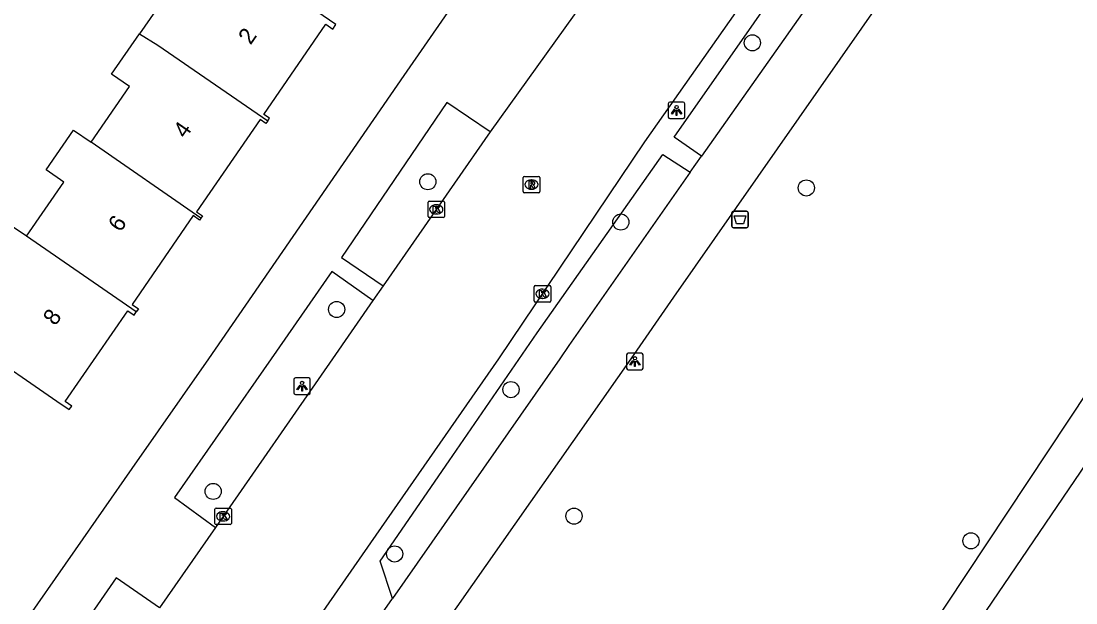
# Model space of a CAD drawing. Extents: x 160158 to 160921, y 381517 to 382041.
# Drawn here: x 160728 to 160791.9, y 381735.2 to 381770.5 of the extents above; entities that cross this region are included whole.
import ezdxf

# ---------------------------------------------------------------- set-up
doc = ezdxf.new("R2010")
doc.units = 0
for name, color, linetype in [('IMGEO_Afvalbak', 7, 'Continuous'), ('IMGEO_Boom', 7, 'Continuous'), ('IMGEO_Fietspad_open', 7, 'Continuous'), ('IMGEO_Kolk', 7, 'Continuous'), ('IMGEO_Lichtpunt', 7, 'Continuous'), ('IMGEO_Loofbos', 7, 'Continuous'), ('IMGEO_Pand', 7, 'Continuous'), ('IMGEO_Pand_nummerreeks', 7, 'Continuous'), ('IMGEO_Rijbaan_lokaal_open', 7, 'Continuous'), ('IMGEO_Rioolput', 7, 'Continuous'), ('IMGEO_Voetpad_open', 7, 'Continuous'), ('IMGEO_Waterloop', 7, 'Continuous')]:
    doc.layers.add(name, color=color, linetype=linetype)

msp = doc.modelspace()

# ---------------------------------------------------------------- linework, layer by layer
at = {"layer": 'IMGEO_Afvalbak'}
for p, q in [((160771.04, 381758.034), (160771.04, 381758.834)), ((160771.04, 381758.834), (160771.04, 381758.034)), ((160771.14, 381758.934), (160771.93, 381758.934)), ((160771.93, 381758.934), (160771.14, 381758.934)), ((160772.03, 381758.834), (160772.03, 381758.034)), ((160772.03, 381758.034), (160772.03, 381758.834)), ((160771.93, 381757.934), (160771.14, 381757.934)), ((160771.14, 381757.934), (160771.93, 381757.934))]:
    msp.add_line(p, q, dxfattribs=at)
msp.add_lwpolyline([(160771.183, 381758.648), (160771.887, 381758.648), (160771.738, 381758.178), (160771.332, 381758.178), (160771.183, 381758.648)], dxfattribs=at)
for centre, start, end in [((160771.14, 381758.834), 90, 180), ((160771.14, 381758.834), 90, 180), ((160771.93, 381758.834), 0, 90), ((160771.93, 381758.834), 360, 90), ((160771.14, 381758.034), 180, 270), ((160771.14, 381758.034), 180, 270), ((160771.93, 381758.034), 270, 0), ((160771.93, 381758.034), 270, 0)]:
    msp.add_arc(centre, 0.1, start, end, dxfattribs=at)
at = {"layer": 'IMGEO_Boom'}
for centre in [(160772.285, 381769.136), (160752.634, 381760.719), (160775.548, 381760.345), (160764.32, 381758.278), (160747.113, 381752.984), (160757.667, 381748.128), (160739.639, 381741.96), (160761.485, 381740.463), (160785.516, 381738.965), (160750.624, 381738.171)]:
    msp.add_circle(centre, 0.489, dxfattribs=at)
at = {"layer": 'IMGEO_Fietspad_open'}
for points in [[(160789.665, 381791.308), (160769.212, 381762.274)], [(160792.763, 381789.478), (160791.434, 381788.016), (160767.517, 381753.72), (160764.918, 381750), (160753.579, 381733.814)], [(160768.522, 381761.29), (160769.212, 381762.274)], [(160768.522, 381761.29), (160761.166, 381750.794), (160760.618, 381750), (160750.493, 381735.463)], [(160747.881, 381731.718), (160750.493, 381735.463)]]:
    msp.add_lwpolyline(points, dxfattribs=at)
at = {"layer": 'IMGEO_Kolk'}
for p, q in [((160752.645, 381758.621), (160752.645, 381759.473)), ((160752.72, 381759.547), (160753.572, 381759.547)), ((160753.133, 381759.327), (160753.158, 381759.327)), ((160753.646, 381759.473), (160753.646, 381758.621)), ((160753.572, 381758.547), (160752.72, 381758.547)), ((160753.156, 381758.767), (160753.131, 381758.767)), ((160759.079, 381753.506), (160759.079, 381754.358)), ((160759.154, 381754.432), (160760.006, 381754.432)), ((160759.567, 381754.212), (160759.592, 381754.212)), ((160760.08, 381754.358), (160760.08, 381753.506)), ((160760.006, 381753.432), (160759.154, 381753.432)), ((160759.59, 381753.652), (160759.565, 381753.652)), ((160739.738, 381740.024), (160739.738, 381740.876)), ((160739.813, 381740.95), (160740.665, 381740.95)), ((160740.226, 381740.73), (160740.251, 381740.73)), ((160740.739, 381740.876), (160740.739, 381740.024)), ((160740.665, 381739.95), (160739.813, 381739.95)), ((160740.249, 381740.17), (160740.224, 381740.17))]:
    msp.add_line(p, q, dxfattribs=at)
for points in [[(160752.645, 381758.621), (160752.645, 381759.473)], [(160752.72, 381759.547), (160753.572, 381759.547)], [(160752.966, 381759.247), (160753.089, 381759.247), (160753.089, 381759.096), (160753.219, 381759.247), (160753.383, 381759.247), (160753.237, 381759.096), (160753.39, 381758.847), (160753.238, 381758.847), (160753.153, 381759.011), (160753.089, 381758.944), (160753.089, 381758.847), (160752.966, 381758.847), (160752.966, 381759.247)], [(160753.646, 381759.473), (160753.646, 381758.621)], [(160753.572, 381758.547), (160752.72, 381758.547)], [(160759.079, 381753.506), (160759.079, 381754.358)], [(160759.154, 381754.432), (160760.006, 381754.432)], [(160759.4, 381754.132), (160759.523, 381754.132), (160759.523, 381753.981), (160759.653, 381754.132), (160759.817, 381754.132), (160759.671, 381753.981), (160759.824, 381753.732), (160759.672, 381753.732), (160759.587, 381753.896), (160759.523, 381753.829), (160759.523, 381753.732), (160759.4, 381753.732), (160759.4, 381754.132)], [(160760.08, 381754.358), (160760.08, 381753.506)], [(160760.006, 381753.432), (160759.154, 381753.432)], [(160739.738, 381740.024), (160739.738, 381740.876)], [(160739.813, 381740.95), (160740.665, 381740.95)], [(160740.059, 381740.65), (160740.182, 381740.65), (160740.182, 381740.499), (160740.312, 381740.65), (160740.476, 381740.65), (160740.33, 381740.499), (160740.483, 381740.25), (160740.331, 381740.25), (160740.246, 381740.414), (160740.182, 381740.347), (160740.182, 381740.25), (160740.059, 381740.25), (160740.059, 381740.65)], [(160740.739, 381740.876), (160740.739, 381740.024)], [(160740.665, 381739.95), (160739.813, 381739.95)]]:
    msp.add_lwpolyline(points, dxfattribs=at)
for centre, start, end in [((160752.722, 381759.471), 91.55205, 178.44795), ((160752.722, 381759.471), 91.55205, 178.44795), ((160753.57, 381759.471), 1.55205, 88.44795), ((160753.57, 381759.471), 1.55205, 88.44795), ((160752.722, 381758.623), 181.55205, 268.44795), ((160752.722, 381758.623), 181.55205, 268.44795), ((160753.57, 381758.623), 271.55205, 358.44795), ((160753.57, 381758.623), 271.55205, 358.44795), ((160759.156, 381754.356), 91.55205, 178.44795), ((160759.156, 381754.356), 91.55205, 178.44795), ((160760.004, 381754.356), 1.55205, 88.44795), ((160760.004, 381754.356), 1.55205, 88.44795), ((160759.156, 381753.508), 181.55205, 268.44795), ((160759.156, 381753.508), 181.55205, 268.44795), ((160760.004, 381753.508), 271.55205, 358.44795), ((160760.004, 381753.508), 271.55205, 358.44795), ((160739.815, 381740.874), 91.55205, 178.44795), ((160739.815, 381740.874), 91.55205, 178.44795), ((160740.663, 381740.874), 1.55205, 88.44795), ((160740.663, 381740.874), 1.55205, 88.44795), ((160739.815, 381740.026), 181.55205, 268.44795), ((160739.815, 381740.026), 181.55205, 268.44795), ((160740.663, 381740.026), 271.55205, 358.44795), ((160740.663, 381740.026), 271.55205, 358.44795)]:
    msp.add_arc(centre, 0.0765, start, end, dxfattribs=at)
for centre, major_axis, ratio, start_param, end_param in [((160753.132, 381759.047), (-0.387, 0.002), 0.722429, 4.712389, 7.853982), ((160753.157, 381759.047), (-0.39, 0.002), 0.717154, 1.570796, 4.712389), ((160759.566, 381753.932), (-0.387, 0.002), 0.722429, 4.712389, 7.853982), ((160759.591, 381753.932), (-0.39, 0.002), 0.717154, 1.570796, 4.712389), ((160740.225, 381740.45), (-0.387, 0.002), 0.722429, 4.712389, 7.853982), ((160740.25, 381740.45), (-0.39, 0.002), 0.717154, 1.570796, 4.712389)]:
    msp.add_ellipse(centre, major_axis=major_axis, ratio=ratio, start_param=start_param, end_param=end_param, dxfattribs=at)
at = {"layer": 'IMGEO_Lichtpunt'}
for p, q in [((160767.194, 381765.448), (160767.194, 381764.641)), ((160767.194, 381765.448), (160767.194, 381764.641)), ((160768.096, 381765.543), (160767.288, 381765.543)), ((160768.096, 381765.543), (160767.288, 381765.543)), ((160768.19, 381764.641), (160768.19, 381765.448)), ((160768.19, 381764.641), (160768.19, 381765.448)), ((160767.288, 381764.547), (160768.096, 381764.547)), ((160767.288, 381764.547), (160768.096, 381764.547)), ((160764.672, 381750.232), (160764.672, 381749.425)), ((160764.672, 381750.232), (160764.672, 381749.425)), ((160765.574, 381750.327), (160764.766, 381750.327)), ((160765.574, 381750.327), (160764.766, 381750.327)), ((160765.668, 381749.425), (160765.668, 381750.232)), ((160765.668, 381749.425), (160765.668, 381750.232)), ((160745.426, 381748.834), (160744.618, 381748.834)), ((160745.426, 381748.834), (160744.618, 381748.834)), ((160764.766, 381749.331), (160765.574, 381749.331)), ((160764.766, 381749.331), (160765.574, 381749.331)), ((160744.524, 381748.739), (160744.524, 381747.932)), ((160744.524, 381748.739), (160744.524, 381747.932)), ((160745.52, 381747.932), (160745.52, 381748.739)), ((160745.52, 381747.932), (160745.52, 381748.739)), ((160744.618, 381747.838), (160745.426, 381747.838)), ((160744.618, 381747.838), (160745.426, 381747.838))]:
    msp.add_line(p, q, dxfattribs=at)
for points in [[(160767.568, 381765.112), (160767.607, 381765.084), (160767.419, 381764.822), (160767.381, 381764.849), (160767.568, 381765.112)], [(160767.67, 381765.064), (160767.717, 381765.064), (160767.717, 381764.742), (160767.67, 381764.742), (160767.67, 381765.064)], [(160767.78, 381765.084), (160767.818, 381765.111), (160768.005, 381764.849), (160767.966, 381764.821), (160767.78, 381765.084)], [(160765.046, 381749.896), (160765.085, 381749.868), (160764.897, 381749.606), (160764.859, 381749.633), (160765.046, 381749.896)], [(160765.148, 381749.848), (160765.195, 381749.848), (160765.195, 381749.526), (160765.148, 381749.526), (160765.148, 381749.848)], [(160765.258, 381749.868), (160765.296, 381749.895), (160765.483, 381749.633), (160765.444, 381749.605), (160765.258, 381749.868)], [(160744.898, 381748.403), (160744.937, 381748.375), (160744.749, 381748.113), (160744.711, 381748.14), (160744.898, 381748.403)], [(160745, 381748.355), (160745.047, 381748.355), (160745.047, 381748.033), (160745, 381748.033), (160745, 381748.355)], [(160745.11, 381748.375), (160745.148, 381748.402), (160745.335, 381748.14), (160745.296, 381748.112), (160745.11, 381748.375)]]:
    msp.add_lwpolyline(points, dxfattribs=at)
for centre in [(160767.693, 381765.246), (160765.171, 381750.03), (160745.023, 381748.537)]:
    msp.add_circle(centre, 0.0994, dxfattribs=at)
for centre, start, end in [((160767.288, 381765.448), 90, 180), ((160767.288, 381765.448), 90, 180), ((160768.096, 381765.448), 0, 90), ((160768.096, 381765.448), 0, 90), ((160767.288, 381764.641), 180, 270), ((160767.288, 381764.641), 180, 270), ((160768.096, 381764.641), 270, 0), ((160768.096, 381764.641), 270, 360), ((160764.766, 381750.232), 90, 180), ((160764.766, 381750.232), 90, 180), ((160765.574, 381750.232), 0, 90), ((160765.574, 381750.232), 0, 90), ((160764.766, 381749.425), 180, 270), ((160764.766, 381749.425), 180, 270), ((160765.574, 381749.425), 270, 0), ((160765.574, 381749.425), 270, 360), ((160744.618, 381748.739), 90, 180), ((160744.618, 381748.739), 90, 180), ((160745.426, 381748.739), 0, 90), ((160745.426, 381748.739), 0, 90), ((160744.618, 381747.932), 180, 270), ((160744.618, 381747.932), 180, 270), ((160745.426, 381747.932), 270, 0), ((160745.426, 381747.932), 270, 360)]:
    msp.add_arc(centre, 0.0946, start, end, dxfattribs=at)
at = {"layer": 'IMGEO_Loofbos'}
msp.add_lwpolyline([(160806.201, 381767.868), (160793.894, 381750), (160774.154, 381720.209)], dxfattribs=at)
at = {"layer": 'IMGEO_Pand'}
for points in [[(160742.941, 381764.412), (160743.047, 381764.566), (160742.704, 381764.802), (160746.455, 381770.258), (160746.878, 381769.967), (160747.068, 381770.245), (160739.262, 381775.612), (160737.435, 381772.955), (160735.18, 381769.69)], [(160732.259, 381763.116), (160734.577, 381766.489), (160733.492, 381767.235), (160735.18, 381769.69)], [(160735.18, 381769.69), (160736.285, 381768.99), (160742.941, 381764.412)], [(160742.941, 381764.412), (160742.832, 381764.253), (160742.481, 381764.494), (160738.63, 381758.892), (160738.985, 381758.648), (160738.9, 381758.523)], [(160728.339, 381757.419), (160730.593, 381760.699), (160729.527, 381761.432), (160731.19, 381763.851), (160732.259, 381763.116)], [(160738.9, 381758.523), (160732.259, 381763.116)], [(160738.9, 381758.523), (160738.813, 381758.397), (160738.423, 381758.666), (160734.726, 381753.288), (160735.116, 381753.02), (160734.985, 381752.83)], [(160728.339, 381757.419), (160727.237, 381758.177), (160723.333, 381752.498), (160719.781, 381754.937), (160717.904, 381752.204), (160723.659, 381748.25), (160725.365, 381750.734), (160730.176, 381747.426), (160730.921, 381746.914), (160731.072, 381747.134), (160730.684, 381747.4), (160734.468, 381752.903), (160734.853, 381752.639), (160734.985, 381752.83)], [(160734.985, 381752.83), (160728.339, 381757.419)]]:
    msp.add_lwpolyline(points, dxfattribs=at)
at = {"layer": 'IMGEO_Rijbaan_lokaal_open'}
for points in [[(160673.052, 381629.169), (160742.168, 381728.75), (160744.459, 381732.031), (160749.187, 381738.841), (160756.939, 381750), (160765.763, 381763.144), (160772.954, 381773.374), (160774.36, 381775.443), (160780.995, 381784.58)], [(160763.193, 381773.21), (160756.409, 381763.749)], [(160753.822, 381770.972), (160751.191, 381767.158), (160739.356, 381750), (160734.718, 381743.353), (160731.28, 381738.425), (160713.812, 381713.39)], [(160756.409, 381763.749), (160753.795, 381765.515), (160747.407, 381756.134), (160749.93, 381754.413)], [(160756.409, 381763.749), (160749.93, 381754.413)], [(160749.312, 381753.522), (160746.826, 381755.275), (160743.151, 381750), (160737.292, 381741.592), (160739.771, 381739.776)], [(160749.93, 381754.413), (160749.312, 381753.522)], [(160749.312, 381753.522), (160746.867, 381750), (160739.771, 381739.776)], [(160739.771, 381739.776), (160736.392, 381734.908)], [(160736.392, 381734.908), (160733.773, 381736.719), (160726.88, 381726.772), (160729.43, 381724.878)]]:
    msp.add_lwpolyline(points, dxfattribs=at)
at = {"layer": 'IMGEO_Rioolput'}
for p, q in [((160758.41, 381760.121), (160758.41, 381760.973)), ((160758.485, 381761.047), (160759.337, 381761.047)), ((160759.411, 381760.973), (160759.411, 381760.121)), ((160758.921, 381760.267), (160758.896, 381760.267)), ((160758.898, 381760.827), (160758.923, 381760.827)), ((160759.337, 381760.047), (160758.485, 381760.047))]:
    msp.add_line(p, q, dxfattribs=at)
for points in [[(160758.41, 381760.121), (160758.41, 381760.973)], [(160758.485, 381761.047), (160759.337, 381761.047)], [(160759.411, 381760.973), (160759.411, 381760.121)], [(160758.999, 381760.745), (160758.747, 381760.747), (160758.747, 381760.347)], [(160758.747, 381760.347), (160758.871, 381760.347), (160758.871, 381760.509), (160758.882, 381760.509)], [(160758.925, 381760.666), (160758.871, 381760.666), (160758.871, 381760.585)], [(160758.871, 381760.585), (160758.923, 381760.585)], [(160758.929, 381760.48), (160759, 381760.347), (160759.14, 381760.347), (160759.075, 381760.473)], [(160759.337, 381760.047), (160758.485, 381760.047)]]:
    msp.add_lwpolyline(points, dxfattribs=at)
for centre, radius, start, end in [((160758.487, 381760.971), 0.0765, 91.55205, 178.44795), ((160758.487, 381760.971), 0.0765, 91.55205, 178.44795), ((160759.335, 381760.971), 0.0765, 1.55205, 88.44795), ((160759.335, 381760.971), 0.0765, 1.55205, 88.44795), ((160758.881, 381760.456), 0.0533, 26.02933, 88.69889), ((160758.907, 381760.774), 0.19, 274.7715, 282.96867), ((160758.931, 381760.57), 0.0964, 77.00612, 93.18647), ((160758.945, 381760.627), 0.0378, 276.66336, 79.67722), ((160758.998, 381760.635), 0.109, 350.36119, 89.41601), ((160758.996, 381760.635), 0.112, 277.58423, 350.98172), ((160758.98, 381760.42), 0.108, 29.51342, 73.79051), ((160758.487, 381760.123), 0.0765, 181.55205, 268.44795), ((160758.487, 381760.123), 0.0765, 181.55205, 268.44795), ((160759.335, 381760.123), 0.0765, 271.55205, 358.44795), ((160759.335, 381760.123), 0.0765, 271.55205, 358.44795)]:
    msp.add_arc(centre, radius, start, end, dxfattribs=at)
for centre, major_axis, ratio, start_param, end_param in [((160758.897, 381760.547), (-0.387, 0.002), 0.722429, 4.712389, 7.853982), ((160758.922, 381760.547), (-0.39, 0.002), 0.717154, 1.570796, 4.712389)]:
    msp.add_ellipse(centre, major_axis=major_axis, ratio=ratio, start_param=start_param, end_param=end_param, dxfattribs=at)
at = {"layer": 'IMGEO_Voetpad_open'}
for points in [[(160769.212, 381762.274), (160767.542, 381763.425), (160777.234, 381777.287), (160787.797, 381792.527), (160789.665, 381791.308)], [(160750.493, 381735.463), (160749.744, 381737.741), (160753.925, 381743.816), (160759.252, 381751.557), (160766.857, 381762.374), (160768.522, 381761.29)]]:
    msp.add_lwpolyline(points, dxfattribs=at)
at = {"layer": 'IMGEO_Waterloop'}
msp.add_lwpolyline([(160775.759, 381718.999), (160796.818, 381750), (160808.219, 381766.786)], dxfattribs=at)

# ---------------------------------------------------------------- texts
at = {"layer": 'IMGEO_Pand_nummerreeks'}
for s, rotation, p in [('2', 55.2274, (160741.903, 381768.969)), ('4', 55.23011, (160737.963, 381763.295)), ('6', 55.23011, (160734.023, 381757.619)), ('8', 55.23011, (160730.085, 381751.946))]:
    msp.add_text(s, height=1, rotation=rotation, dxfattribs=at).set_placement(p)

doc.saveas('drawing.dxf')
